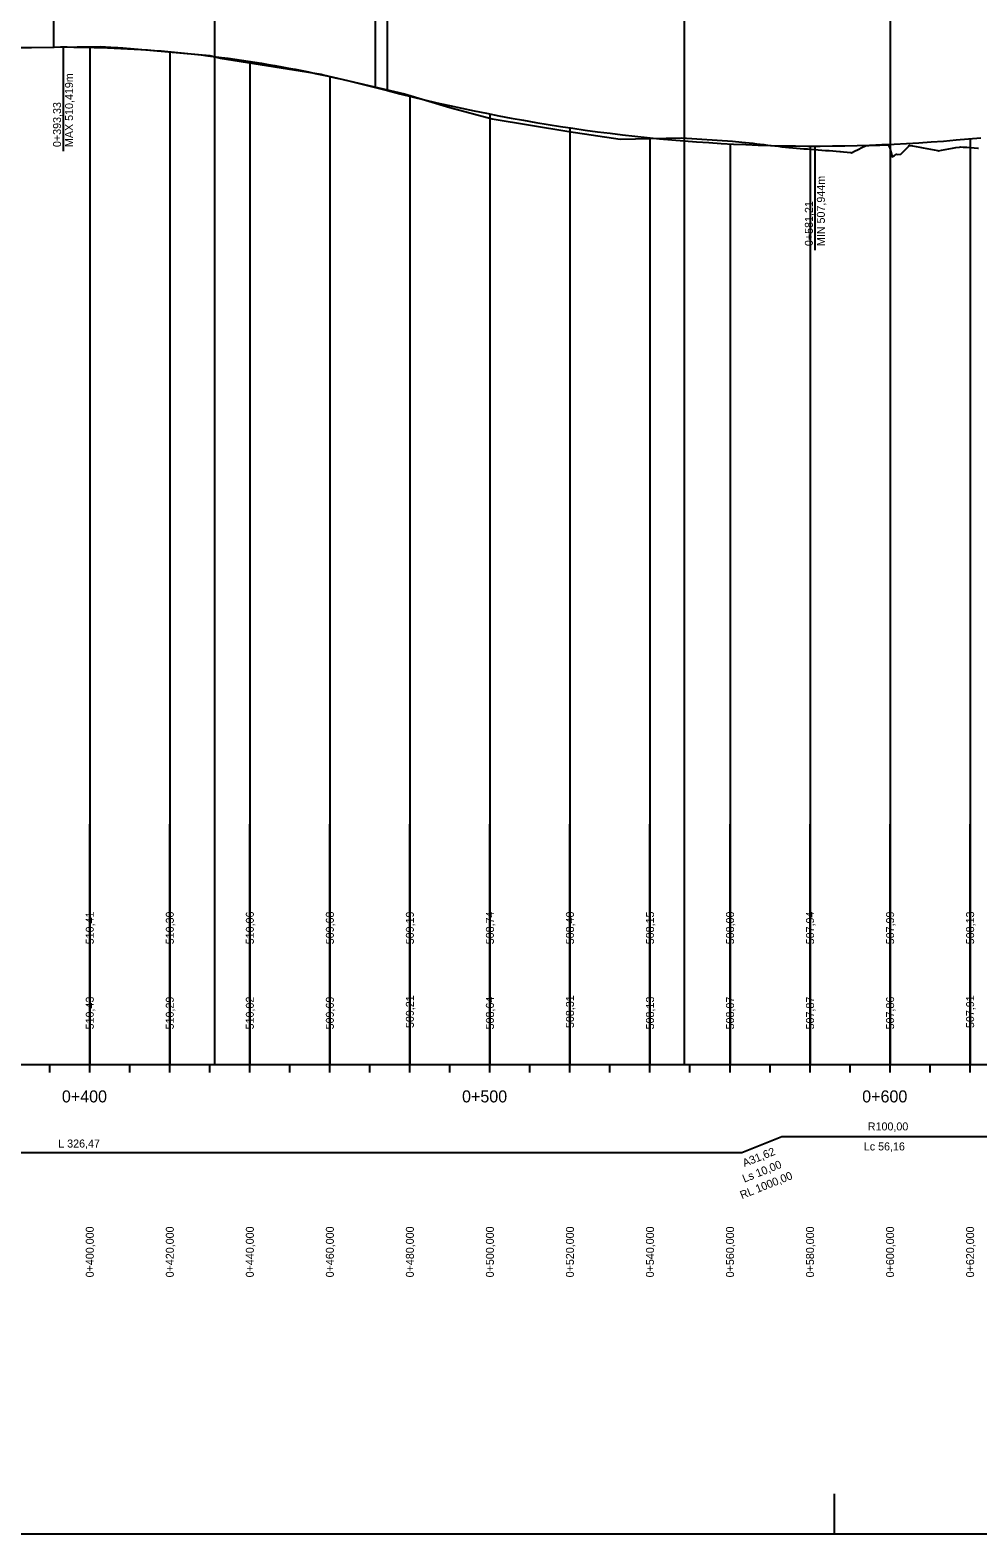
# Model space of a CAD drawing. Extents: x -632716 to -629545, y -1094726 to -1088285.
# Drawn here: x -632225.7 to -631988.8, y -1093689.1 to -1093313.3 of the extents above; entities that cross this region are included whole.
import ezdxf

# ---------------------------------------------------------------- set-up
doc = ezdxf.new("R2010")
doc.units = 0
for name, color, linetype in [('20', 7, 'Continuous'), ('Default', 7, 'Continuous'), ('formát', 7, 'Continuous'), ('NIVELETA_VYSKY', 7, 'Continuous'), ('REZ_POPIS', 7, 'Continuous'), ('REZ_TABULKA', 7, 'Continuous'), ('REZ_TENKA', 7, 'Continuous'), ('REZ_TLUSTA', 7, 'Continuous'), ('SKLONY_NIVELETA', 7, 'Continuous'), ('SKLONY_POPIS', 7, 'Continuous'), ('TECNY_NIVELETA', 7, 'Continuous'), ('TEREN_VYSKY', 7, 'Continuous'), ('VOZOVKA', 7, 'Continuous')]:
    doc.layers.add(name, color=color, linetype=linetype)

msp = doc.modelspace()

# ---------------------------------------------------------------- linework, layer by layer
at = {"layer": '20'}
for points in [[(-632210.75, -1093317.62), (-632210.75, -1093521.74), (-632210.75, -1093571.74), (-632210.75, -1093511.74)], [(-632190.75, -1093318.73), (-632190.75, -1093521.74), (-632190.75, -1093571.74), (-632190.75, -1093511.74)], [(-632170.75, -1093321.16), (-632170.75, -1093521.74), (-632170.75, -1093571.74), (-632170.75, -1093511.74)], [(-632150.75, -1093324.93), (-632150.75, -1093521.74), (-632150.75, -1093571.74), (-632150.75, -1093511.74)], [(-632130.75, -1093329.86), (-632130.75, -1093521.74), (-632130.75, -1093571.74), (-632130.75, -1093511.74)], [(-632110.75, -1093334.29), (-632110.75, -1093521.74), (-632110.75, -1093571.74), (-632110.75, -1093511.74)], [(-632090.75, -1093337.74), (-632090.75, -1093521.74), (-632090.75, -1093571.74), (-632090.75, -1093511.74)], [(-632070.75, -1093340.23), (-632070.75, -1093521.74), (-632070.75, -1093571.74), (-632070.75, -1093511.74)], [(-632050.75, -1093341.75), (-632050.75, -1093521.74), (-632050.75, -1093571.74), (-632050.75, -1093511.74)], [(-632030.75, -1093342.29), (-632030.75, -1093521.74), (-632030.75, -1093571.74), (-632030.75, -1093511.74)], [(-632010.75, -1093341.86), (-632010.75, -1093521.74), (-632010.75, -1093571.74), (-632010.75, -1093511.74)], [(-631990.75, -1093340.47), (-631990.75, -1093521.74), (-631990.75, -1093571.74), (-631990.75, -1093511.74)]]:
    msp.add_lwpolyline(points, dxfattribs=at)
at = {"layer": 'Default'}
for p, q in [((-632234.05, -1093317.67), (-632219.73, -1093317.56)), ((-632234.05, -1093317.67), (-632219.73, -1093317.56)), ((-632139.34, -1093327.67), (-632136.33, -1093328.45)), ((-632139.34, -1093327.67), (-632136.33, -1093328.45))]:
    msp.add_line(p, q, dxfattribs=at)
for points in [[(-632219.73, -1093317.56), (-632218.05, -1093317.55), (-632216.38, -1093317.55), (-632214.7, -1093317.56), (-632213.03, -1093317.58), (-632211.35, -1093317.61), (-632209.68, -1093317.65), (-632208, -1093317.69), (-632206.33, -1093317.75), (-632204.66, -1093317.82), (-632202.98, -1093317.89), (-632201.31, -1093317.98), (-632199.63, -1093318.07), (-632197.96, -1093318.18), (-632196.28, -1093318.29), (-632194.61, -1093318.41), (-632192.93, -1093318.54), (-632191.26, -1093318.68), (-632189.58, -1093318.83), (-632187.91, -1093318.99), (-632186.23, -1093319.16), (-632184.56, -1093319.34), (-632182.88, -1093319.53), (-632181.21, -1093319.72), (-632177.86, -1093320.15), (-632176.19, -1093320.37), (-632174.51, -1093320.6), (-632172.84, -1093320.85), (-632171.16, -1093321.1), (-632169.49, -1093321.36), (-632167.81, -1093321.63), (-632166.14, -1093321.91), (-632164.46, -1093322.2), (-632162.79, -1093322.5), (-632161.11, -1093322.81), (-632159.44, -1093323.13), (-632157.77, -1093323.46), (-632156.09, -1093323.79), (-632154.42, -1093324.14), (-632152.74, -1093324.49), (-632151.07, -1093324.86), (-632149.39, -1093325.23), (-632147.72, -1093325.61), (-632146.04, -1093326.01), (-632144.37, -1093326.41), (-632142.69, -1093326.82), (-632141.02, -1093327.24), (-632139.34, -1093327.67)], [(-632219.73, -1093317.56), (-632218.05, -1093317.55), (-632216.38, -1093317.55), (-632214.7, -1093317.56), (-632213.03, -1093317.58), (-632211.35, -1093317.61), (-632209.68, -1093317.65), (-632208, -1093317.69), (-632206.33, -1093317.75), (-632204.66, -1093317.82), (-632202.98, -1093317.89), (-632201.31, -1093317.98), (-632199.63, -1093318.07), (-632197.96, -1093318.18), (-632196.28, -1093318.29), (-632194.61, -1093318.41), (-632192.93, -1093318.54), (-632191.26, -1093318.68), (-632189.58, -1093318.83), (-632187.91, -1093318.99), (-632186.23, -1093319.16), (-632184.56, -1093319.34), (-632182.88, -1093319.53), (-632181.21, -1093319.72), (-632177.86, -1093320.15), (-632176.19, -1093320.37), (-632174.51, -1093320.6), (-632172.84, -1093320.85), (-632171.16, -1093321.1), (-632169.49, -1093321.36), (-632167.81, -1093321.63), (-632166.14, -1093321.91), (-632164.46, -1093322.2), (-632162.79, -1093322.5), (-632161.11, -1093322.81), (-632159.44, -1093323.13), (-632157.77, -1093323.46), (-632156.09, -1093323.79), (-632154.42, -1093324.14), (-632152.74, -1093324.49), (-632151.07, -1093324.86), (-632149.39, -1093325.23), (-632147.72, -1093325.61), (-632146.04, -1093326.01), (-632144.37, -1093326.41), (-632142.69, -1093326.82), (-632141.02, -1093327.24), (-632139.34, -1093327.67)], [(-632136.33, -1093328.45), (-632133.24, -1093329.24), (-632130.15, -1093330.01), (-632127.07, -1093330.75), (-632123.98, -1093331.47), (-632120.89, -1093332.16), (-632117.8, -1093332.84), (-632114.71, -1093333.49), (-632111.62, -1093334.11), (-632108.54, -1093334.72), (-632105.45, -1093335.3), (-632102.36, -1093335.86), (-632099.27, -1093336.39), (-632096.18, -1093336.9), (-632093.1, -1093337.39), (-632090.01, -1093337.85), (-632086.92, -1093338.3), (-632083.83, -1093338.72), (-632080.74, -1093339.11), (-632077.65, -1093339.48), (-632074.57, -1093339.83), (-632071.48, -1093340.16), (-632068.39, -1093340.46), (-632065.3, -1093340.74), (-632059.13, -1093341.23), (-632056.04, -1093341.44), (-632052.95, -1093341.63), (-632049.86, -1093341.79), (-632046.77, -1093341.93), (-632043.68, -1093342.05), (-632040.6, -1093342.14), (-632037.51, -1093342.22), (-632034.42, -1093342.26), (-632031.33, -1093342.29), (-632028.24, -1093342.29), (-632025.16, -1093342.27), (-632022.07, -1093342.22), (-632018.98, -1093342.16), (-632015.89, -1093342.07), (-632012.8, -1093341.95), (-632009.71, -1093341.82), (-632006.63, -1093341.66), (-632003.54, -1093341.47), (-632000.45, -1093341.27), (-631997.36, -1093341.04), (-631994.27, -1093340.78), (-631991.19, -1093340.51), (-631988.1, -1093340.21)], [(-632136.33, -1093328.45), (-632133.24, -1093329.24), (-632130.15, -1093330.01), (-632127.07, -1093330.75), (-632123.98, -1093331.47), (-632120.89, -1093332.16), (-632117.8, -1093332.84), (-632114.71, -1093333.49), (-632111.62, -1093334.11), (-632108.54, -1093334.72), (-632105.45, -1093335.3), (-632102.36, -1093335.86), (-632099.27, -1093336.39), (-632096.18, -1093336.9), (-632093.1, -1093337.39), (-632090.01, -1093337.85), (-632086.92, -1093338.3), (-632083.83, -1093338.72), (-632080.74, -1093339.11), (-632077.65, -1093339.48), (-632074.57, -1093339.83), (-632071.48, -1093340.16), (-632068.39, -1093340.46), (-632065.3, -1093340.74), (-632059.13, -1093341.23), (-632056.04, -1093341.44), (-632052.95, -1093341.63), (-632049.86, -1093341.79), (-632046.77, -1093341.93), (-632043.68, -1093342.05), (-632040.6, -1093342.14), (-632037.51, -1093342.22), (-632034.42, -1093342.26), (-632031.33, -1093342.29), (-632028.24, -1093342.29), (-632025.16, -1093342.27), (-632022.07, -1093342.22), (-632018.98, -1093342.16), (-632015.89, -1093342.07), (-632012.8, -1093341.95), (-632009.71, -1093341.82), (-632006.63, -1093341.66), (-632003.54, -1093341.47), (-632000.45, -1093341.27), (-631997.36, -1093341.04), (-631994.27, -1093340.78), (-631991.19, -1093340.51), (-631988.1, -1093340.21)]]:
    msp.add_lwpolyline(points, dxfattribs=at)
at = {"layer": 'formát'}
msp.add_line((-632024.61, -1093689.05), (-632024.61, -1093679.05), dxfattribs=at)
msp.add_lwpolyline([(-632715.96, -1093689.05), (-630764.61, -1093689.05), (-630764.61, -1093095.05), (-632715.96, -1093095.05)], close=True, dxfattribs=at)
at = {"layer": 'REZ_TABULKA'}
msp.add_lwpolyline([(-632374.23, -1093593.74), (-632047.76, -1093593.74), (-632047.76, -1093593.74), (-632037.76, -1093589.74), (-632037.76, -1093589.74), (-631981.6, -1093589.74), (-631981.6, -1093589.74), (-631971.6, -1093593.74), (-631971.6, -1093593.74), (-631738.82, -1093593.74)], dxfattribs=at)
at = {"layer": 'REZ_TENKA'}
for p, q in [((-632220.75, -1093573.74), (-632220.75, -1093571.74)), ((-632200.75, -1093573.74), (-632200.75, -1093571.74)), ((-632190.75, -1093573.74), (-632190.75, -1093571.74)), ((-632180.75, -1093573.74), (-632180.75, -1093571.74)), ((-632170.75, -1093573.74), (-632170.75, -1093571.74)), ((-632160.75, -1093573.74), (-632160.75, -1093571.74)), ((-632150.75, -1093573.74), (-632150.75, -1093571.74)), ((-632140.75, -1093573.74), (-632140.75, -1093571.74)), ((-632130.75, -1093573.74), (-632130.75, -1093571.74)), ((-632120.75, -1093573.74), (-632120.75, -1093571.74)), ((-632100.75, -1093573.74), (-632100.75, -1093571.74)), ((-632090.75, -1093573.74), (-632090.75, -1093571.74)), ((-632080.75, -1093573.74), (-632080.75, -1093571.74)), ((-632070.75, -1093573.74), (-632070.75, -1093571.74)), ((-632060.75, -1093573.74), (-632060.75, -1093571.74)), ((-632050.75, -1093573.74), (-632050.75, -1093571.74)), ((-632040.75, -1093573.74), (-632040.75, -1093571.74)), ((-632030.75, -1093573.74), (-632030.75, -1093571.74)), ((-632020.75, -1093573.74), (-632020.75, -1093571.74)), ((-632000.75, -1093573.74), (-632000.75, -1093571.74)), ((-631990.75, -1093573.74), (-631990.75, -1093571.74))]:
    msp.add_line(p, q, dxfattribs=at)
at = {"layer": 'REZ_TLUSTA'}
for p, q in [((-632610.75, -1093571.74), (-631190.75, -1093571.74)), ((-632210.75, -1093573.74), (-632210.75, -1093569.74)), ((-632110.75, -1093573.74), (-632110.75, -1093569.74)), ((-632010.75, -1093573.74), (-632010.75, -1093569.74))]:
    msp.add_line(p, q, dxfattribs=at)
at = {"layer": 'SKLONY_NIVELETA'}
for p, q in [((-632010.75, -1093182.47), (-632010.75, -1093341.86)), ((-632179.54, -1093217.25), (-632179.54, -1093571.74)), ((-632062.21, -1093247.67), (-632062.21, -1093571.74)), ((-632234.05, -1093317.67), (-632219.73, -1093317.56)), ((-632139.34, -1093327.67), (-632136.33, -1093328.45))]:
    msp.add_line(p, q, dxfattribs=at)
for points in [[(-632219.73, -1093317.56), (-632218.05, -1093317.55), (-632216.38, -1093317.55), (-632214.7, -1093317.56), (-632213.03, -1093317.58), (-632211.35, -1093317.61), (-632209.68, -1093317.65), (-632208, -1093317.69), (-632206.33, -1093317.75), (-632204.66, -1093317.82), (-632202.98, -1093317.89), (-632201.31, -1093317.98), (-632199.63, -1093318.07), (-632197.96, -1093318.18), (-632196.28, -1093318.29), (-632194.61, -1093318.41), (-632192.93, -1093318.54), (-632191.26, -1093318.68), (-632189.58, -1093318.83), (-632187.91, -1093318.99), (-632186.23, -1093319.16), (-632184.56, -1093319.34), (-632182.88, -1093319.53), (-632181.21, -1093319.72), (-632177.86, -1093320.15), (-632176.19, -1093320.37), (-632174.51, -1093320.6), (-632172.84, -1093320.85), (-632171.16, -1093321.1), (-632169.49, -1093321.36), (-632167.81, -1093321.63), (-632166.14, -1093321.91), (-632164.46, -1093322.2), (-632162.79, -1093322.5), (-632161.11, -1093322.81), (-632159.44, -1093323.13), (-632157.77, -1093323.46), (-632156.09, -1093323.79), (-632154.42, -1093324.14), (-632152.74, -1093324.49), (-632151.07, -1093324.86), (-632149.39, -1093325.23), (-632147.72, -1093325.61), (-632146.04, -1093326.01), (-632144.37, -1093326.41), (-632142.69, -1093326.82), (-632141.02, -1093327.24), (-632139.34, -1093327.67)], [(-632136.33, -1093328.45), (-632133.24, -1093329.24), (-632130.15, -1093330.01), (-632127.07, -1093330.75), (-632123.98, -1093331.47), (-632120.89, -1093332.16), (-632117.8, -1093332.84), (-632114.71, -1093333.49), (-632111.62, -1093334.11), (-632108.54, -1093334.72), (-632105.45, -1093335.3), (-632102.36, -1093335.86), (-632099.27, -1093336.39), (-632096.18, -1093336.9), (-632093.1, -1093337.39), (-632090.01, -1093337.85), (-632086.92, -1093338.3), (-632083.83, -1093338.72), (-632080.74, -1093339.11), (-632077.65, -1093339.48), (-632074.57, -1093339.83), (-632071.48, -1093340.16), (-632068.39, -1093340.46), (-632065.3, -1093340.74), (-632059.13, -1093341.23), (-632056.04, -1093341.44), (-632052.95, -1093341.63), (-632049.86, -1093341.79), (-632046.77, -1093341.93), (-632043.68, -1093342.05), (-632040.6, -1093342.14), (-632037.51, -1093342.22), (-632034.42, -1093342.26), (-632031.33, -1093342.29), (-632028.24, -1093342.29), (-632025.16, -1093342.27), (-632022.07, -1093342.22), (-632018.98, -1093342.16), (-632015.89, -1093342.07), (-632012.8, -1093341.95), (-632009.71, -1093341.82), (-632006.63, -1093341.66), (-632003.54, -1093341.47), (-632000.45, -1093341.27), (-631997.36, -1093341.04), (-631994.27, -1093340.78), (-631991.19, -1093340.51), (-631988.1, -1093340.21)]]:
    msp.add_lwpolyline(points, dxfattribs=at)
at = {"layer": 'TECNY_NIVELETA'}
for p, q in [((-632219.73, -1093317.56), (-632219.73, -1093216.56)), ((-632139.34, -1093327.67), (-632139.34, -1093226.67)), ((-632136.33, -1093328.45), (-632136.33, -1093227.45)), ((-632217.43, -1093317.55), (-632217.43, -1093343.55)), ((-632029.54, -1093342.29), (-632029.54, -1093368.29))]:
    msp.add_line(p, q, dxfattribs=at)
at = {"layer": 'VOZOVKA'}
msp.add_lwpolyline([(-632236.92, -1093317.83), (-632208.14, -1093317.42), (-632205.47, -1093317.62), (-632203.75, -1093317.72), (-632202.45, -1093317.75), (-632194.81, -1093318.46), (-632180.73, -1093319.64), (-632178.19, -1093320.34), (-632152.96, -1093324.36), (-632152.41, -1093324.47), (-632132.11, -1093329.25), (-632120.76, -1093332.69), (-632110.15, -1093335.51), (-632091.06, -1093338.63), (-632078.16, -1093340.58), (-632062.9, -1093340.26), (-632050.1, -1093341.05), (-632047.76, -1093341.31), (-632046.86, -1093341.42), (-632045.95, -1093341.52), (-632045.04, -1093341.62), (-632044.13, -1093341.73), (-632043.22, -1093341.83), (-632042.31, -1093341.93), (-632041.4, -1093342.04), (-632040.49, -1093342.14), (-632039.58, -1093342.25), (-632038.67, -1093342.35), (-632037.76, -1093342.46), (-632036.86, -1093342.56), (-632036.04, -1093342.66), (-632035.95, -1093342.67), (-632035.05, -1093342.74), (-632034.14, -1093342.81), (-632033.24, -1093342.88), (-632032.33, -1093342.96), (-632031.42, -1093343.03), (-632030.52, -1093343.1), (-632029.61, -1093343.17), (-632028.71, -1093343.24), (-632027.8, -1093343.31), (-632026.9, -1093343.38), (-632025.99, -1093343.45), (-632025.08, -1093343.52), (-632024.18, -1093343.59), (-632023.27, -1093343.66), (-632023.15, -1093343.67), (-632022.37, -1093343.76), (-632021.46, -1093343.85), (-632020.55, -1093343.95), (-632020.42, -1093343.97), (-632019.65, -1093343.59), (-632018.74, -1093343.14), (-632017.84, -1093342.7), (-632016.93, -1093342.27), (-632016.73, -1093342.17), (-632016.03, -1093342.15), (-632015.12, -1093342.12), (-632014.21, -1093342.09), (-632013.31, -1093342.06), (-632012.4, -1093342.03), (-632011.5, -1093342), (-632011.26, -1093341.99), (-632010.83, -1093342.87), (-632010.59, -1093343.72), (-632010.24, -1093344.97), (-632009.68, -1093344.66), (-632009.14, -1093344.36), (-632008.81, -1093344.38), (-632008.78, -1093344.38), (-632008.08, -1093344.37), (-632007.87, -1093344.16), (-632006.97, -1093343.23), (-632006.06, -1093342.29), (-632005.94, -1093342.16), (-632005.92, -1093342.12), (-632005.91, -1093342.12), (-632005.82, -1093342.14), (-632005.71, -1093342.16), (-632005.16, -1093342.27), (-632004.25, -1093342.44), (-632003.34, -1093342.6), (-632002.44, -1093342.77), (-632001.53, -1093342.94), (-632000.63, -1093343.1), (-631999.72, -1093343.26), (-631998.82, -1093343.43), (-631998.65, -1093343.46), (-631997.91, -1093343.33), (-631997, -1093343.17), (-631996.1, -1093343.01), (-631995.19, -1093342.86), (-631994.29, -1093342.7), (-631993.38, -1093342.54), (-631993.09, -1093342.5), (-631992.47, -1093342.54), (-631991.57, -1093342.61), (-631990.66, -1093342.67), (-631989.76, -1093342.73), (-631988.85, -1093342.79), (-631988.67, -1093342.8)], dxfattribs=at)

# ---------------------------------------------------------------- texts
at = {"layer": 'NIVELETA_VYSKY'}
for s, p in [('510,41', (-632209.75, -1093541.74)), ('510,30', (-632189.75, -1093541.74)), ('510,06', (-632169.75, -1093541.74)), ('509,68', (-632149.75, -1093541.74)), ('509,19', (-632129.75, -1093541.74)), ('508,74', (-632109.75, -1093541.74)), ('508,40', (-632089.75, -1093541.74)), ('508,15', (-632069.75, -1093541.74)), ('508,00', (-632049.75, -1093541.74)), ('507,94', (-632029.75, -1093541.74)), ('507,99', (-632009.75, -1093541.74)), ('508,13', (-631989.75, -1093541.74))]:
    msp.add_text(s, height=2, rotation=90, dxfattribs=at).set_placement(p)
at = {"layer": 'REZ_POPIS'}
for s, p in [('0+400', (-632217.71, -1093581.24)), ('0+500', (-632117.71, -1093581.24)), ('0+600', (-632017.71, -1093581.24))]:
    msp.add_text(s, height=3, dxfattribs=at).set_placement(p)
at = {"layer": 'REZ_TABULKA'}
for s, p in [('R100,00', (-632016.31, -1093588.24)), ('L 326,47', (-632218.62, -1093592.52)), ('Lc 56,16', (-632017.31, -1093593.24))]:
    msp.add_text(s, height=2, dxfattribs=at).set_placement(p)
for s, rotation, p in [('A31,62', 21.8014, (-632047.13, -1093597.41)), ('Ls 10,00', 21.8014, (-632047.17, -1093601.3)), ('RL 1000,00', 21.8014, (-632047.77, -1093605.42)), ('0+400,000', 90, (-632209.75, -1093624.95)), ('0+420,000', 90, (-632189.75, -1093624.95)), ('0+440,000', 90, (-632169.75, -1093624.95)), ('0+460,000', 90, (-632149.75, -1093624.95)), ('0+480,000', 90, (-632129.75, -1093624.95)), ('0+500,000', 90, (-632109.75, -1093624.95)), ('0+520,000', 90, (-632089.75, -1093624.95)), ('0+540,000', 90, (-632069.75, -1093624.95)), ('0+560,000', 90, (-632049.75, -1093624.95)), ('0+580,000', 90, (-632029.75, -1093624.95)), ('0+600,000', 90, (-632009.75, -1093624.95)), ('0+620,000', 90, (-631989.75, -1093624.95))]:
    msp.add_text(s, height=2, rotation=rotation, dxfattribs=at).set_placement(p)
at = {"layer": 'SKLONY_POPIS'}
for s, p in [('MAX 510,419m', (-632214.93, -1093342.55)), ('0+393,33', (-632217.93, -1093342.55)), ('MIN 507,944m', (-632027.04, -1093367.29)), ('0+581,21', (-632030.04, -1093367.29))]:
    msp.add_text(s, height=2, rotation=90, dxfattribs=at).set_placement(p)
at = {"layer": 'TEREN_VYSKY'}
for s, p in [('510,43', (-632209.75, -1093563)), ('510,29', (-632189.75, -1093563)), ('510,02', (-632169.75, -1093563)), ('509,69', (-632149.75, -1093563)), ('509,21', (-632129.75, -1093562.66)), ('508,64', (-632109.75, -1093563)), ('508,31', (-632089.75, -1093562.66)), ('508,13', (-632069.75, -1093563)), ('508,07', (-632049.75, -1093563)), ('507,87', (-632029.75, -1093563)), ('507,86', (-632009.75, -1093563)), ('507,91', (-631989.75, -1093562.66))]:
    msp.add_text(s, height=2, rotation=90, dxfattribs=at).set_placement(p)

doc.saveas('drawing.dxf')
